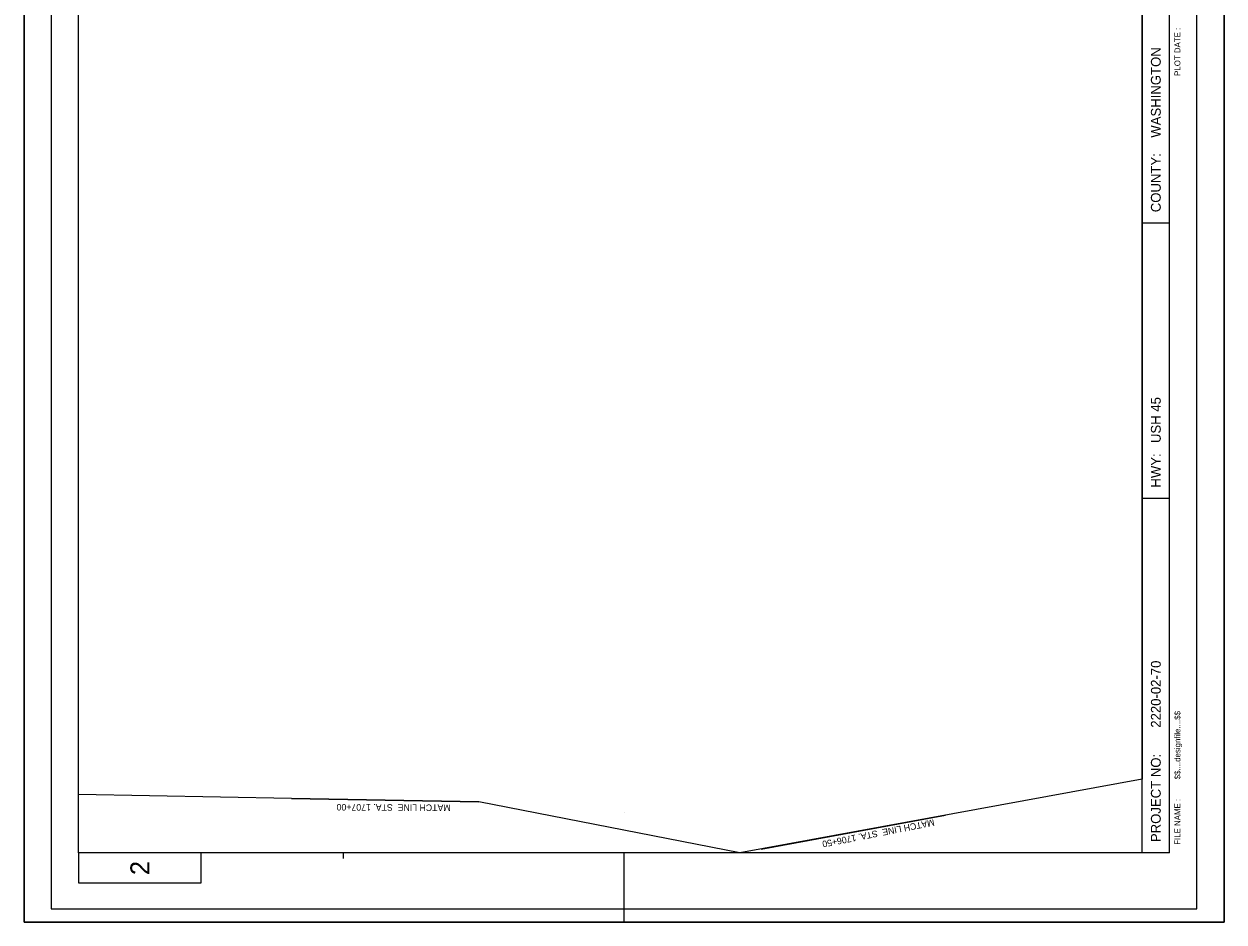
# Model space of a CAD drawing. Extents: x 361080 to 362180, y 129788 to 131488.
# Drawn here: x 361080 to 362180, y 129788 to 130611 of the extents above; entities that cross this region are included whole.
import ezdxf

# ---------------------------------------------------------------- set-up
doc = ezdxf.new("R2010")
doc.units = 0
for name, color, linetype in [('Default', 7, 'Continuous'), ('P_SHTIDX_1 [KAPUR_CADDS_LEVELS]', 7, 'Continuous'), ('P_SHTIDX_2 [KAPUR_CADDS_LEVELS]', 7, 'Continuous'), ('P_SHTIDX_3 [KAPUR_CADDS_LEVELS]', 7, 'Continuous'), ('P_TXT_Plan 2 [KAPUR_CADDS_LEVELS]', 7, 'Continuous'), ('P_TXT_Plan 3 [KAPUR_CADDS_LEVELS]', 7, 'Continuous'), ('P_TXT_Plan 4 [KAPUR_CADDS_LEVELS]', 7, 'Continuous')]:
    doc.layers.add(name, color=color, linetype=linetype)

msp = doc.modelspace()

# ---------------------------------------------------------------- linework, layer by layer
at = {"layer": 'Default'}
msp.add_lwpolyline([(361325.4, 129901.1), (361130.1, 129904.7), (361130.1, 131405.5), (361490.1, 131398.9), (361588.3, 131403.7), (361726, 131415), (361860.5, 131426.1), (362105.1, 131426.1), (362105.1, 129918.8), (361736.3, 129851.1), (361497.1, 129898)], close=True, dxfattribs=at)
msp.add_lwpolyline([(361325.4, 129901.1), (361130.1, 129904.7), (361130.1, 131405.5), (361490.1, 131398.9), (361588.3, 131403.7), (361726, 131415), (361860.5, 131426.1), (362105.1, 131426.1), (362105.1, 129918.8), (361736.3, 129851.1), (361497.1, 129898)], close=True, dxfattribs=at)
msp.add_lwpolyline([(361325.4, 129901.1), (361130.1, 129904.7), (361130.1, 131405.5), (361490.1, 131398.9), (361588.3, 131403.7), (361726, 131415), (361860.5, 131426.1), (362105.1, 131426.1), (362105.1, 129918.8), (361736.3, 129851.1), (361497.1, 129898)], close=True, dxfattribs=at)
msp.add_lwpolyline([(361325.4, 129901.1), (361130.1, 129904.7), (361130.1, 131405.5), (361490.1, 131398.9), (361588.3, 131403.7), (361726, 131415), (361860.5, 131426.1), (362105.1, 131426.1), (362105.1, 129918.8), (361736.3, 129851.1), (361497.1, 129898)], close=True, dxfattribs=at)
msp.add_lwpolyline([(361325.4, 129901.1), (361130.1, 129904.7), (361130.1, 131405.5), (361490.1, 131398.9), (361588.3, 131403.7), (361726, 131415), (361860.5, 131426.1), (362105.1, 131426.1), (362105.1, 129918.8), (361736.3, 129851.1), (361497.1, 129898)], close=True, dxfattribs=at)
msp.add_lwpolyline([(361325.4, 129901.1), (361130.1, 129904.7), (361130.1, 131405.5), (361490.1, 131398.9), (361588.3, 131403.7), (361726, 131415), (361860.5, 131426.1), (362105.1, 131426.1), (362105.1, 129918.8), (361736.3, 129851.1), (361497.1, 129898)], close=True, dxfattribs=at)
msp.add_lwpolyline([(361325.4, 129901.1), (361130.1, 129904.7), (361130.1, 131405.5), (361490.1, 131398.9), (361588.3, 131403.7), (361726, 131415), (361860.5, 131426.1), (362105.1, 131426.1), (362105.1, 129918.8), (361736.3, 129851.1), (361497.1, 129898)], close=True, dxfattribs=at)
msp.add_lwpolyline([(361325.4, 129901.1), (361130.1, 129904.7), (361130.1, 131405.5), (361490.1, 131398.9), (361588.3, 131403.7), (361726, 131415), (361860.5, 131426.1), (362105.1, 131426.1), (362105.1, 129918.8), (361736.3, 129851.1), (361497.1, 129898)], close=True, dxfattribs=at)
at = {"layer": 'P_SHTIDX_1 [KAPUR_CADDS_LEVELS]'}
msp.add_lwpolyline([(361080.1, 129787.8), (361080.1, 131487.8), (362180.1, 131487.8), (362180.1, 129787.8), (361080.1, 129787.8)], dxfattribs=at)
at = {"layer": 'P_SHTIDX_2 [KAPUR_CADDS_LEVELS]'}
for p, q in [((361130.1, 129851.1), (361130.1, 131426.1)), ((362105.1, 129851.1), (362105.1, 131426.1)), ((362130.1, 129851.1), (362130.1, 131426.1)), ((362130.1, 130428.6), (362105.1, 130428.6)), ((362130.1, 130176.1), (362105.1, 130176.1)), ((361630.1, 129888.6), (361630.1, 129888.6)), ((362130.1, 129851.1), (361130.1, 129851.1)), ((361372.6, 129851.1), (361372.6, 129846.1)), ((361630.1, 129787.8), (361630.1, 129851.1)), ((361080.1, 129787.8), (361080.1, 129837.8)), ((362180.1, 129787.8), (362180.1, 129837.8)), ((361130.1, 129787.8), (361080.1, 129787.8)), ((361655.1, 129787.8), (361605.1, 129787.8)), ((362180.1, 129787.8), (362130.1, 129787.8))]:
    msp.add_line(p, q, dxfattribs=at)
msp.add_lwpolyline([(361130.1, 129851.1), (361130.1, 129823.6), (361242.6, 129823.6), (361242.6, 129851.1)], close=True, dxfattribs=at)
at = {"layer": 'P_SHTIDX_3 [KAPUR_CADDS_LEVELS]'}
for points in [[(362180.1, 129787.8), (362180.1, 131487.8), (361080.1, 131487.8), (361080.1, 129787.8)], [(362155.1, 129799.8), (362155.1, 131454.8), (361105.1, 131454.8), (361105.1, 129799.8)]]:
    msp.add_lwpolyline(points, close=True, dxfattribs=at)
at = {"layer": 'P_TXT_Plan 3 [KAPUR_CADDS_LEVELS]'}
for p, q in [((361325.4, 129901.1), (361497.1, 129898)), ((361755.9, 129854.7), (361924.8, 129885.7))]:
    msp.add_line(p, q, dxfattribs=at)
at = {"layer": 'P_TXT_Plan 4 [KAPUR_CADDS_LEVELS]'}
msp.add_lwpolyline([(361080.1, 129787.8), (361080.1, 131487.8), (362180.1, 131487.8), (362180.1, 129787.8)], close=True, dxfattribs=at)

# ---------------------------------------------------------------- texts
at = {"layer": 'P_SHTIDX_2 [KAPUR_CADDS_LEVELS]'}
for s, height, p in [('PLOT DATE :', 5.4, (362140.1, 130563.6)), (' WASHINGTON', 9, (362122.1, 130503.6)), ('COUNTY:', 9, (362122.1, 130438.6)), (' USH 45', 9, (362122.1, 130223.6)), ('HWY:', 9, (362122.1, 130186.1)), (' 2220-02-70', 9, (362122.1, 129962.6)), ('$$....designfile....$$', 5.4, (362140.1, 129918.6)), ('PROJECT NO:', 9, (362122.1, 129861.1)), ('FILE NAME :', 5.4, (362140.1, 129858.6)), ('2', 17.5, (361195.1, 129830.8))]:
    msp.add_text(s, height=height, rotation=90, dxfattribs=at).set_placement(p)
at = {"layer": 'P_TXT_Plan 2 [KAPUR_CADDS_LEVELS]'}
for s, rotation, p in [('MATCH LINE  STA. 1707+00', 179.6776, (361471.2, 129895.5)), ('MATCH LINE  STA. 1706+50', 191.1335, (361914, 129882.2))]:
    msp.add_text(s, height=6, rotation=rotation, dxfattribs=at).set_placement(p)

doc.saveas('drawing.dxf')
